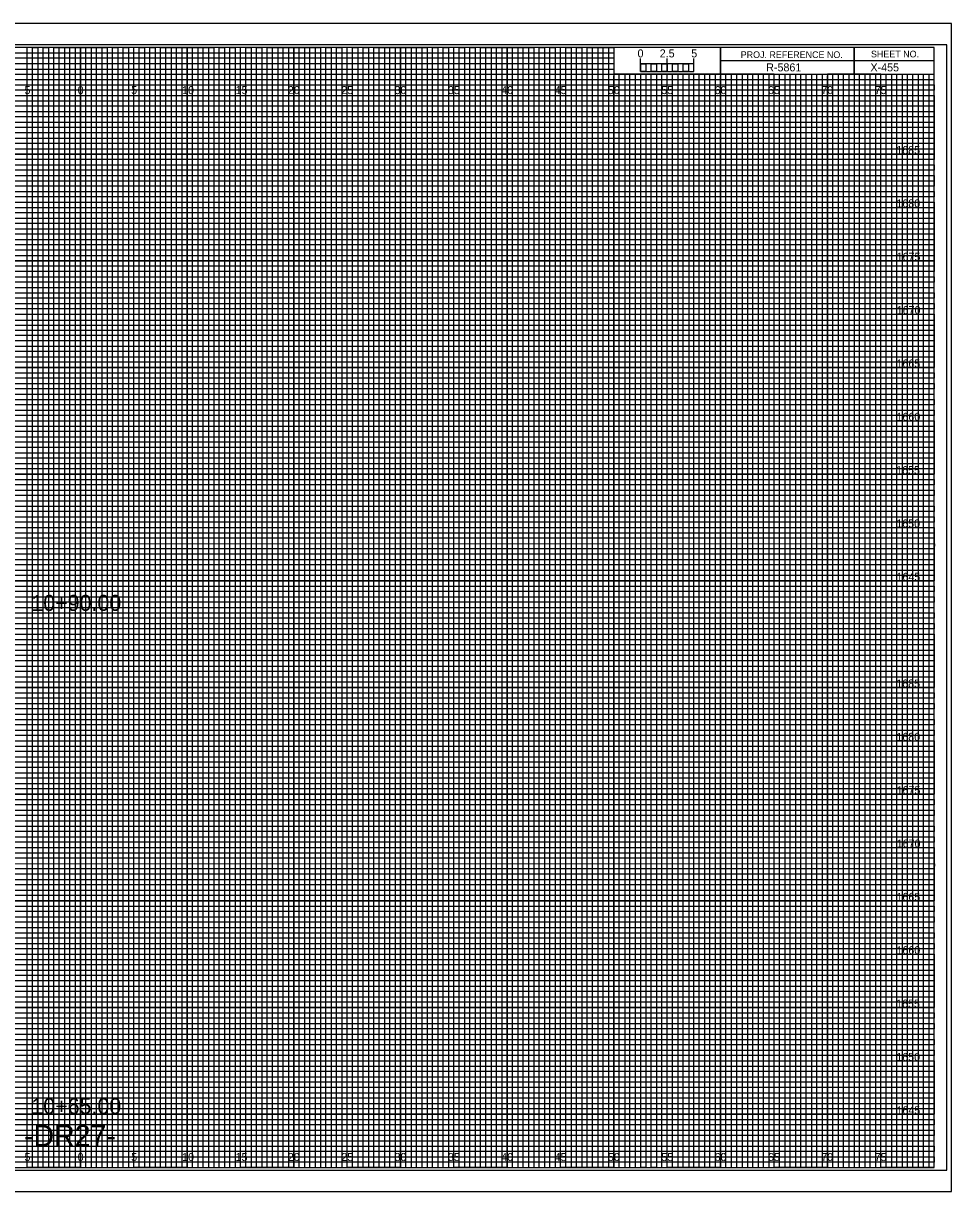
# Model space of a CAD drawing. Extents: x -7 to 162, y -2 to 217.
# Drawn here: x 74.6 to 161.7, y 107.7 to 217.2 of the extents above; entities that cross this region are included whole.
import ezdxf

# ---------------------------------------------------------------- set-up
doc = ezdxf.new("R2010")
doc.units = 0
for name, color, linetype in [('Prop Horizontal Alignment', 7, 'Continuous'), ('Prop XS Alignment Label', 7, 'Continuous'), ('Prop XS Bar Scale Labels', 7, 'Continuous'), ('Prop XS Gore Control Minimum', 7, 'Continuous'), ('Prop XS Project Number', 7, 'Continuous'), ('Prop XS Sheet Number', 7, 'Continuous'), ('Raster_Level_0', 7, 'Continuous'), ('Scratch_Level_3', 7, 'Continuous'), ('Sheet Cross Section CELL', 7, 'Continuous'), ('Sheet Cross Section Grid Middle CELL', 7, 'Continuous'), ('Sheet Cross Section Grid Minor 1 CELL', 7, 'Continuous'), ('Sheet Cross Section Grid Minor 2 CELL', 7, 'Continuous'), ('Sheet Cross Section Scale CELL', 7, 'Continuous'), ('Sheet Cutting Line CELL', 7, 'Continuous'), ('Sheet DOT Grid CELL', 7, 'Continuous'), ('Sheet Plot Border Inside CELL', 7, 'Continuous'), ('Sheet Plot Border Outside CELL', 7, 'Continuous')]:
    doc.layers.add(name, color=color, linetype=linetype)

msp = doc.modelspace()

# ---------------------------------------------------------------- linework, layer by layer
at = {"layer": 'Prop XS Gore Control Minimum'}
for p, q in [((75, 215), (70, 215)), ((75, 110), (75, 215)), ((85, 215), (80, 215)), ((80, 215), (80, 110)), ((85, 110), (85, 215)), ((95, 215), (90, 215)), ((90, 215), (90, 110)), ((95, 110), (95, 215)), ((105, 215), (100, 215)), ((100, 215), (100, 110)), ((105, 110), (105, 215)), ((115, 215), (110, 215)), ((110, 215), (110, 110)), ((115, 110), (115, 215)), ((125, 215), (120, 215)), ((120, 215), (120, 110)), ((125, 110), (125, 215)), ((130, 215), (130, 110)), ((135, 110), (135, 212.5)), ((145, 212.5), (140, 212.5)), ((140, 212.5), (140, 110)), ((145, 110), (145, 212.5)), ((155, 212.5), (150, 212.5)), ((150, 212.5), (150, 110)), ((155, 110), (155, 212.5)), ((80, 110), (75, 110)), ((90, 110), (85, 110)), ((100, 110), (95, 110)), ((110, 110), (105, 110)), ((120, 110), (115, 110)), ((130, 110), (125, 110)), ((140, 110), (135, 110)), ((150, 110), (145, 110)), ((160, 110), (155, 110)), ((160, 110), (160, 110))]:
    msp.add_line(p, q, dxfattribs=at)
for points in [[(0, 210), (160, 210), (160, 205), (0, 205)], [(0, 200), (160, 200), (160, 195), (0, 195)], [(0, 190), (160, 190), (160, 185), (0, 185)], [(0, 180), (160, 180), (160, 175), (0, 175)], [(0, 170), (160, 170), (160, 165), (0, 165)], [(0, 160), (160, 160), (160, 155), (0, 155)], [(0, 150), (160, 150), (160, 145), (0, 145)], [(0, 140), (160, 140), (160, 135), (0, 135)], [(0, 130), (160, 130), (160, 125), (0, 125)], [(0, 120), (160, 120), (160, 115), (0, 115)]]:
    msp.add_lwpolyline(points, dxfattribs=at)
at = {"layer": 'Sheet Cross Section CELL'}
for p, q in [((152.5, 215), (152.5, 212.5)), ((152.5, 212.5), (152.5, 215)), ((160, 213.75), (140, 213.75)), ((140, 213.75), (140, 212.5)), ((140, 212.5), (160, 212.5))]:
    msp.add_line(p, q, dxfattribs=at)
for points in [[(160, 215), (0, 215), (0, 110), (160, 110)], [(140, 215), (130, 215), (130, 212.52), (140, 212.52)], [(160, 215), (140, 215), (140, 212.5), (160, 212.5)]]:
    msp.add_lwpolyline(points, close=True, dxfattribs=at)
at = {"layer": 'Sheet Cross Section Grid Middle CELL'}
for points in [[(72.5, 110), (77.5, 110), (77.5, 215), (82.5, 215), (82.5, 110), (87.5, 110), (87.5, 215), (92.5, 215), (92.5, 110), (97.5, 110), (97.5, 215), (102.5, 215), (102.5, 110), (107.5, 110), (107.5, 215), (112.5, 215), (112.5, 110), (117.5, 110), (117.5, 215), (122.5, 215), (122.5, 110), (127.5, 110), (127.5, 215), (129.97, 215), (130, 215), (130, 212.5), (132.5, 212.5), (132.5, 110), (137.5, 110), (137.5, 212.5), (142.5, 212.5), (142.5, 110), (147.5, 110), (147.5, 212.5), (152.5, 212.5), (152.5, 110), (157.5, 110), (157.5, 212.5)], [(0, 212.5), (137.5, 212.5)], [(0, 202.5), (160, 202.5), (160, 207.5), (0, 207.5)], [(0, 192.5), (160, 192.5), (160, 197.5), (0, 197.5)], [(0, 182.5), (160, 182.5), (160, 187.5), (0, 187.5)], [(0, 172.5), (160, 172.5), (160, 177.5), (0, 177.5)], [(0, 162.5), (160, 162.5), (160, 167.5), (0, 167.5)], [(0, 152.5), (160, 152.5), (160, 157.5), (0, 157.5)], [(0, 142.5), (160, 142.5), (160, 147.5), (0, 147.5)], [(0, 132.5), (160, 132.5), (160, 137.5), (0, 137.5)], [(0, 122.5), (160, 122.5), (160, 127.5), (0, 127.5)], [(0, 112.5), (160, 112.5), (160, 117.5), (0, 117.5)]]:
    msp.add_lwpolyline(points, dxfattribs=at)
at = {"layer": 'Sheet Cross Section Grid Minor 1 CELL'}
for p, q in [((0, 214.5), (130, 214.5)), ((130, 213.99), (0, 213.99)), ((130, 214.5), (130, 213.99)), ((0, 213.5), (130, 213.5)), ((130, 212.94), (0, 212.94)), ((130, 213.5), (130, 212.94)), ((0, 212), (160, 212))]:
    msp.add_line(p, q, dxfattribs=at)
for points in [[(0, 211.5), (135, 211.5), (160, 211.5), (160, 211), (0, 211)], [(0, 210.5), (160, 210.5), (160, 209.5), (0, 209.5)], [(0, 209), (160, 209), (160, 208.5), (0, 208.49)], [(0, 208), (160, 208), (160, 207), (0, 207)], [(0, 206.5), (160, 206.5), (160, 206), (0, 206)], [(0, 205.5), (160, 205.5), (160, 204.5), (0, 204.5)], [(0, 204), (160, 204), (160, 203.5), (0, 203.5)], [(0, 203), (160, 203), (160, 202), (0, 202)], [(0, 201.5), (160, 201.5), (160, 201), (0, 201)], [(0, 200.5), (160, 200.5), (160, 199.5), (0, 199.5)], [(0, 199), (160, 199), (160, 198.5), (0, 198.5)], [(0, 198), (160, 198), (160, 196.97), (160, 196.5), (160, 196), (0, 196)], [(0, 197), (160, 197), (160, 196.5), (0, 196.5)], [(0, 195.5), (160, 195.5), (160, 194.5), (0, 194.52)], [(0, 194.52), (160, 194.5), (160, 194), (0, 194)], [(0, 193.5), (160, 193.5), (160, 193), (0, 193)], [(0, 192), (160, 192), (160, 191.5), (0, 191.5)], [(0, 191), (160, 191), (160, 190.5), (0, 190.5)], [(-0.04, 189.44), (160, 189.44), (160, 188.94), (-0.04, 188.94)], [(0, 188.5), (160, 188.5), (160, 188), (0, 188)], [(0, 187), (160, 187), (160, 186.5), (0, 186.5)], [(0, 186), (160, 186), (160, 185.5), (0, 185.5)], [(0, 184.5), (160, 184.5), (160, 184), (0, 184)], [(0, 183.5), (160, 183.5), (160, 183), (0, 183)], [(0, 182), (160, 182), (160, 181.5), (0, 181.5)], [(0, 181), (160, 181), (160, 180.5), (0, 180.5)], [(0, 179.5), (160, 179.5), (160, 178.99), (0, 179)], [(0, 178.5), (160, 178.5), (160, 178), (0, 178)], [(0, 177), (160, 177), (160, 176.5), (0, 176.5)], [(0, 176), (160, 176), (160, 175.5), (0, 175.5)], [(0, 174.5), (160, 174.5), (160, 174), (0, 174)], [(0, 173.5), (160, 173.5), (160, 173), (0, 173)], [(0, 172), (160, 172), (160, 171.5), (0, 171.5)], [(0, 171), (160, 171), (160, 170.5), (0, 170.5)], [(0, 169.5), (160, 169.5), (160, 169), (0, 169)], [(0, 168.5), (160.03, 168.46), (160, 168), (0, 168)], [(0, 167), (160, 167), (160, 166.5), (0, 166.5)], [(0, 166), (160, 166), (160, 165.5), (0, 165.5)], [(0, 164.5), (160, 164.5), (160, 164), (0, 164)], [(0, 163.5), (160, 163.5), (160, 163), (0, 163)], [(0, 162), (160, 162), (160, 161.5), (0, 161.5)], [(0, 161), (160, 161), (160, 160.5), (0, 160.5)], [(0, 159.5), (160, 159.5), (160, 159), (0, 159)], [(0, 158.5), (160, 158.5), (160, 158), (0, 158)], [(0, 157), (160, 157), (160, 156.5), (0, 156.5)], [(0, 156), (160, 156), (160, 155.5), (0, 155.5)], [(0, 154.5), (160, 154.5), (160, 154), (0, 154)], [(0, 153.5), (160, 153.5), (160, 153), (0, 153)], [(0, 152), (160, 152), (160, 151.5), (0, 151.5)], [(0, 151), (160, 151), (160, 150.5), (0, 150.5)], [(0, 149.5), (160, 149.5), (160, 148.99), (0, 149)], [(0, 148.5), (160, 148.5), (160, 148), (0, 148)], [(0, 147), (160, 147), (160, 146.5), (0, 146.5)], [(0, 146), (160, 146), (160, 145.5), (0, 145.5)], [(0, 144.5), (160, 144.5), (160, 144), (0, 144)], [(0, 143.5), (160, 143.5), (160, 143), (0, 143)], [(0, 142), (160, 142), (160, 141.5), (0, 141.5)], [(0, 141), (160, 141), (160, 140.5), (0, 140.5)], [(0, 139.5), (160, 139.5), (160, 139), (0, 139)], [(0, 138.5), (160.03, 138.46), (160, 138), (0, 138)], [(0, 137), (160, 137), (160, 136.5), (0, 136.5)], [(0, 136), (160, 136), (160, 135.5), (0, 135.5)], [(0, 134.5), (160, 134.5), (160, 134), (0, 134)], [(0, 133.5), (160, 133.5), (160, 133), (0, 133)], [(0, 132), (160, 132), (160, 131.5), (0, 131.5)], [(0, 131), (160, 131), (160, 130.5), (0, 130.5)], [(0, 129.5), (160, 129.5), (160, 129), (0, 129)], [(0, 128.5), (160, 128.5), (160, 128), (0, 128)], [(0, 127), (160, 127), (160, 126.5), (0, 126.5)], [(0, 126), (160, 126), (160, 125.5), (0, 125.5)], [(0, 124.5), (160, 124.5), (160, 124), (0, 124)], [(0, 123.5), (160, 123.5), (160, 123), (0, 123)], [(0, 122), (160, 122), (160, 121.5), (0, 121.5)], [(0, 121), (160, 121), (160, 120.5), (0, 120.5)], [(0, 119.5), (160, 119.5), (160, 119), (0, 119)], [(0, 118.5), (160, 118.5), (160, 118), (0, 118)], [(0, 117), (160, 117), (160, 116.5), (0, 116.5)], [(0, 116), (160, 116), (160, 115.5), (0, 115.5)], [(0, 114.5), (160, 114.5), (160, 114), (0, 114)], [(0, 113.5), (160, 113.5), (160, 113), (0, 113)], [(0, 112), (160, 112), (160, 111.5), (0, 111.5)], [(0, 111), (160, 111), (160, 110.5), (0, 110.5)]]:
    msp.add_lwpolyline(points, dxfattribs=at)
at = {"layer": 'Sheet Cross Section Grid Minor 2 CELL'}
for p, q in [((133.5, 212.5), (133, 212.5)), ((133, 212.5), (133, 110)), ((133.5, 110), (133.5, 212.5)), ((134.5, 212.5), (134, 212.5)), ((134, 212.5), (134, 110)), ((134.5, 110), (134.5, 212.5)), ((133, 110), (132.5, 110)), ((134, 110), (133.5, 110))]:
    msp.add_line(p, q, dxfattribs=at)
for points in [[(75, 110), (75.5, 110), (75.5, 215), (76, 215), (76, 110)], [(76, 110), (76.5, 110), (76.5, 215), (77, 215), (77, 110)], [(77.5, 110), (78, 110), (78, 215), (78.5, 215), (78.5, 110)], [(78.5, 110), (79, 110), (79, 215), (79.5, 215), (79.5, 110)], [(80, 110), (80.5, 110), (80.5, 215), (81, 215), (81, 110)], [(81, 110), (81.5, 110), (81.5, 215), (82, 215), (82, 110)], [(82.5, 110), (83, 110), (83, 215), (83.5, 215), (83.5, 110)], [(83.5, 110), (84, 110), (84, 215), (84.5, 215), (84.5, 110)], [(85, 110), (85.5, 110), (85.5, 215), (86, 215), (86, 110)], [(86, 110), (86.5, 110), (86.5, 215), (87, 215), (87, 110)], [(87.5, 110), (88, 110), (88, 215), (88.5, 215), (88.5, 110)], [(88.5, 110), (89, 110), (89, 215), (89.5, 215), (89.5, 110)], [(90, 110), (90.5, 110), (90.5, 215), (91, 215), (91, 110)], [(91, 110), (91.5, 110), (91.5, 215), (92, 215), (92, 110)], [(92.5, 110), (93, 110), (93, 215), (93.5, 215), (93.5, 110)], [(93.5, 110), (94, 110), (94, 215), (94.5, 215), (94.5, 110)], [(95, 110), (95.5, 110), (95.5, 215), (96, 215), (96, 110)], [(96, 110), (96.5, 110), (96.5, 215), (97, 215), (97, 110)], [(97.5, 110), (98, 110), (98, 215), (98.5, 215), (98.5, 110)], [(98.5, 110), (99, 110), (99, 215), (99.5, 215), (99.5, 110)], [(100, 110), (100.5, 110), (100.5, 215), (101, 215), (101, 110)], [(101, 110), (101.5, 110), (101.5, 215), (102, 215), (102, 110)], [(102.5, 110), (103, 110), (103, 215), (103.5, 215), (103.5, 110)], [(103.5, 110), (104, 110), (104, 215), (104.5, 215), (104.5, 110)], [(105, 110), (105.5, 110), (105.5, 215), (106, 215), (106, 110)], [(106, 110), (106.5, 110), (106.5, 215), (107, 215), (107, 110)], [(107.5, 110), (108, 110), (108, 215), (108.5, 215), (108.5, 110)], [(108.5, 110), (109, 110), (109, 215), (109.5, 215), (109.5, 110)], [(110, 110), (110.5, 110), (110.5, 215), (111, 215), (111, 110)], [(111, 110), (111.5, 110), (111.5, 215), (112, 215), (112, 110)], [(112.5, 110), (113, 110), (113, 215), (113.5, 215), (113.5, 110)], [(113.5, 110), (114, 110), (114, 215), (114.5, 215), (114.5, 110)], [(115, 110), (115.5, 110), (115.5, 215), (116, 215), (116, 110)], [(116, 110), (116.5, 110), (116.5, 215), (117, 215), (117, 110)], [(117.5, 110), (118, 110), (118, 215), (118.5, 215), (118.5, 110)], [(118.5, 110), (119, 110), (119, 215), (119.5, 215), (119.5, 110)], [(120, 110), (120.5, 110), (120.5, 215), (121, 215), (121, 110)], [(121, 110), (121.5, 110), (121.5, 215), (122, 215), (122, 110)], [(122.5, 110), (123, 110), (123, 215), (123.5, 215), (123.5, 110)], [(123.5, 110), (124, 110), (124, 215), (124.5, 215), (124.5, 110)], [(125, 110), (125.5, 110), (125.5, 215), (126, 215), (126, 110)], [(126, 110), (126.5, 110), (126.5, 215), (127, 215), (127, 110)], [(127.5, 110), (128, 110), (128, 215), (128.5, 215), (128.5, 110)], [(128.5, 110), (129, 110), (129, 215), (129.5, 215), (129.5, 110)], [(130, 110), (130.5, 110), (130.5, 212.5), (131.01, 212.5), (131.01, 110)], [(131, 110), (131.5, 110), (131.5, 212.5), (132, 212.5), (132, 110)], [(135, 110), (135.49, 110), (135.49, 212.5), (136, 212.5), (136, 110)], [(136, 110), (136.5, 110), (136.5, 212.5), (137.03, 212.5), (137.03, 110)], [(137.5, 110), (138, 110), (138, 212.5), (138.5, 212.5), (138.5, 110)], [(138.5, 110), (139, 110), (139, 212.5), (139.5, 212.5), (139.5, 110)], [(140, 110), (140.5, 110), (140.5, 212.5), (141, 212.5), (141, 110)], [(141, 110), (141.5, 110), (141.5, 212.5), (142, 212.5), (142, 110)], [(142.5, 110), (143, 110), (143, 212.5), (143.5, 212.5), (143.5, 110)], [(143.5, 110), (144, 110), (144, 212.5), (144.5, 212.5), (144.5, 110)], [(145, 110), (145.5, 110), (145.5, 212.5), (146, 212.5), (146, 110)], [(146, 110), (146.5, 110), (146.5, 212.5), (147, 212.5), (147, 110)], [(147.5, 110), (148, 110), (148, 212.5), (148.5, 212.5), (148.5, 110)], [(148.5, 110), (149, 110), (149, 212.5), (149.5, 212.5), (149.5, 110)], [(150, 110), (150.5, 110), (150.5, 212.5), (151, 212.5), (151, 110)], [(151, 110), (151.5, 110), (151.5, 212.5), (152, 212.5), (152, 110)], [(152.5, 110), (153, 110), (153, 212.5), (153.5, 212.5), (153.5, 110)], [(153.5, 110), (154, 110), (154, 212.5), (154.5, 212.5), (154.5, 110)], [(155, 110), (155.5, 110), (155.5, 212.5), (156, 212.5), (156, 110)], [(156, 110), (156.5, 110), (156.5, 212.5), (157, 212.5), (157, 110)], [(157.5, 110), (158, 110), (158, 212.5), (158.5, 212.5), (158.5, 110)], [(158.5, 110), (159, 110), (159, 212.5), (159.5, 212.5), (159.5, 110)]]:
    msp.add_lwpolyline(points, dxfattribs=at)
at = {"layer": 'Sheet Cross Section Scale CELL'}
for p, q in [((132.5, 212.75), (132.5, 213.95)), ((132.5, 213.45), (132.5, 213.95)), ((135, 212.75), (135, 213.95)), ((137.5, 212.75), (137.5, 213.95)), ((137.5, 213.45), (137.5, 213.95))]:
    msp.add_line(p, q, dxfattribs=at)
for points in [[(137.5, 213.45), (132.5, 213.45), (132.5, 212.75), (137.5, 212.75)], [(132.5, 213.45), (133, 213.45), (133, 212.75), (132.5, 212.75)], [(133.5, 213.45), (134, 213.45), (134, 212.75), (133.5, 212.75)], [(134.5, 213.45), (135, 213.45), (135, 212.75), (134.5, 212.75)], [(135.5, 213.45), (136, 213.45), (136, 212.75), (135.5, 212.75)], [(136.5, 213.45), (137, 213.45), (137, 212.75), (136.5, 212.75)]]:
    msp.add_lwpolyline(points, close=True, dxfattribs=at)
at = {"layer": 'Sheet Cutting Line CELL'}
for p, q in [((161.65, 217.25), (-6.7, 217.25)), ((-6.7, 107.75), (161.65, 107.75))]:
    msp.add_line(p, q, dxfattribs=at)
at = {"layer": 'Sheet DOT Grid CELL'}
for p, q in [((75, 110), (75, 215)), ((80, 110), (80, 215)), ((85, 110), (85, 215)), ((90, 110), (90, 215)), ((95, 110), (95, 215)), ((100, 110), (100, 215)), ((105, 110), (105, 215)), ((110, 110), (110, 215)), ((115, 110), (115, 215)), ((120, 110), (120, 215)), ((125, 110), (125, 215)), ((130, 110), (130, 212.34)), ((135, 110), (135, 212.34)), ((140, 110), (140, 212.34)), ((145, 110), (145, 212.34)), ((150, 110), (150, 212.34)), ((155, 110), (155, 212.34)), ((0, 210), (160, 210)), ((0, 205), (160, 205)), ((0, 200), (160, 200)), ((0, 195), (160, 195)), ((0, 190), (160, 190)), ((0, 185), (160, 185)), ((0, 180), (160, 180)), ((0, 175), (160, 175)), ((0, 170), (160, 170)), ((0, 165), (160, 165)), ((0, 160), (160, 160)), ((0, 155), (160, 155)), ((0, 150), (160, 150)), ((0, 145), (160, 145)), ((0, 140), (160, 140)), ((0, 135), (160, 135)), ((0, 130), (160, 130)), ((0, 125), (160, 125)), ((0, 120), (160, 120)), ((0, 115), (160, 115))]:
    msp.add_line(p, q, dxfattribs=at)
at = {"layer": 'Sheet Plot Border Inside CELL'}
msp.add_lwpolyline([(-5.4, 109.75), (161.2, 109.75), (161.2, 215.25), (-5.4, 215.25)], close=True, dxfattribs=at)
at = {"layer": 'Sheet Plot Border Outside CELL'}
msp.add_lwpolyline([(-6.7, 107.75), (161.65, 107.75), (161.65, 217.25), (-6.7, 217.25)], close=True, dxfattribs=at)

# ---------------------------------------------------------------- texts
at = {"layer": 'Prop Horizontal Alignment'}
for s, p in [('10+90.00', (75.39, 162.18)), ('10+65.00', (75.39, 115.02))]:
    msp.add_text(s, height=1.5, dxfattribs=at).set_placement(p)
at = {"layer": 'Prop XS Alignment Label'}
msp.add_text('-DR27-', height=2, dxfattribs=at).set_placement((74.7, 112))
at = {"layer": 'Prop XS Bar Scale Labels'}
for s, p in [('2.5', (134.29, 214.06)), ('5', (137.24, 214.06))]:
    msp.add_text(s, height=0.75, dxfattribs=at).set_placement(p)
at = {"layer": 'Prop XS Project Number'}
msp.add_text('R-5861', height=0.75, dxfattribs=at).set_placement((144.27, 212.75))
at = {"layer": 'Prop XS Sheet Number'}
msp.add_text('X-455', height=0.75, dxfattribs=at).set_placement((154.04, 212.75))
at = {"layer": 'Raster_Level_0'}
for s, p in [('5', (74.74, 210.62)), ('0', (79.73, 210.62)), ('0', (79.73, 210.62)), ('5', (84.74, 210.62)), ('10', (89.52, 210.62)), ('15', (94.53, 210.62)), ('20', (99.43, 210.62)), ('25', (104.44, 210.62)), ('30', (109.43, 210.62)), ('35', (114.44, 210.62)), ('40', (119.43, 210.62)), ('45', (124.44, 210.62)), ('50', (129.43, 210.62)), ('55', (134.44, 210.62)), ('60', (139.43, 210.62)), ('65', (144.44, 210.62)), ('70', (149.43, 210.62)), ('75', (154.44, 210.62)), ('5', (74.74, 110.62)), ('0', (79.73, 110.62)), ('0', (79.73, 110.62)), ('5', (84.74, 110.62)), ('10', (89.52, 110.62)), ('15', (94.53, 110.62)), ('20', (99.43, 110.62)), ('25', (104.44, 110.62)), ('30', (109.43, 110.62)), ('35', (114.44, 110.62)), ('40', (119.43, 110.62)), ('45', (124.44, 110.62)), ('50', (129.43, 110.62)), ('55', (134.44, 110.62)), ('60', (139.43, 110.62)), ('65', (144.44, 110.62)), ('70', (149.43, 110.62)), ('75', (154.44, 110.62))]:
    msp.add_text(s, height=0.75, dxfattribs=at).set_placement(p)
at = {"layer": 'Scratch_Level_3'}
for s, p in [('1685', (156.46, 205)), ('1680', (156.47, 200)), ('1675', (156.49, 195)), ('1670', (156.5, 190)), ('1665', (156.48, 185)), ('1660', (156.48, 180)), ('1655', (156.45, 175)), ('1650', (156.46, 170)), ('1645', (156.48, 165)), ('1685', (156.46, 155)), ('1680', (156.47, 150)), ('1675', (156.49, 145)), ('1670', (156.5, 140)), ('1665', (156.48, 135)), ('1660', (156.48, 130)), ('1655', (156.45, 125)), ('1650', (156.46, 120)), ('1645', (156.48, 115))]:
    msp.add_text(s, height=0.75, dxfattribs=at).set_placement(p)
at = {"layer": 'Sheet Cross Section CELL'}
for s, p in [('PROJ. REFERENCE NO.', (141.88, 214)), ('SHEET NO.', (154.09, 214.06))]:
    msp.add_text(s, height=0.625, dxfattribs=at).set_placement(p)
at = {"layer": 'Sheet Cross Section Scale CELL'}
msp.add_text('0', height=0.75, dxfattribs=at).set_placement((132.21, 214.06))

doc.saveas('drawing.dxf')
